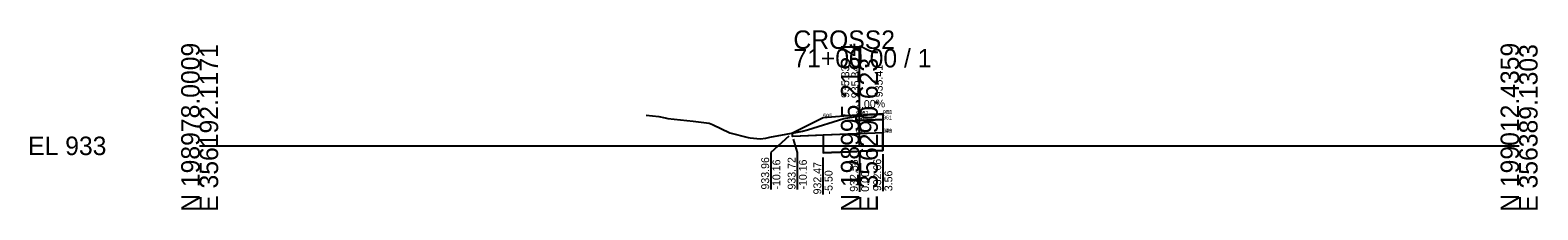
# Model space of a CAD drawing. Extents: x -26 to 203, y -10 to 14021.
# Drawn here: x -25.7 to 202.8, y 11990.3 to 12017.5 of the extents above; entities that cross this region are included whole.
import ezdxf

# ---------------------------------------------------------------- set-up
doc = ezdxf.new("R2010")
doc.units = 0
for name, color, linetype in [('Default', 7, 'Continuous'), ('P_E_XS_Ground', 7, 'Continuous'), ('P_XS', 7, 'Continuous'), ('P_XS_Bold', 7, 'Continuous'), ('P_XS_EAR_CommonGrnd', 7, 'Continuous'), ('P_XS_Lane', 7, 'Continuous'), ('P_XS_Rock', 7, 'Continuous')]:
    doc.layers.add(name, color=color, linetype=linetype)

msp = doc.modelspace()

# ---------------------------------------------------------------- linework, layer by layer
at = {"layer": 'Default'}
for p, q in [((100, 12000), (100, 12014.68)), ((0, 12000), (100, 12000)), ((100, 12000), (200, 12000))]:
    msp.add_line(p, q, dxfattribs=at)
at = {"layer": 'P_E_XS_Ground'}
for p, q in [((101.22, 12004.71), (103.54, 12004.89)), ((103.54, 12004.89), (103.65, 12004.89)), ((67.67, 12004.66), (69.59, 12004.44)), ((69.59, 12004.44), (70.55, 12004.23)), ((70.55, 12004.23), (70.99, 12004.15)), ((70.99, 12004.15), (74.78, 12003.73)), ((74.78, 12003.73), (77.25, 12003.45)), ((77.25, 12003.45), (77.74, 12003.21)), ((77.74, 12003.21), (80.35, 12001.99)), ((92.15, 12002.41), (97.63, 12004.14)), ((97.63, 12004.14), (97.95, 12004.19)), ((97.95, 12004.19), (100, 12004.54)), ((100, 12004.54), (100.86, 12004.68)), ((100.86, 12004.68), (101.22, 12004.71)), ((80.35, 12001.99), (83.14, 12001.25)), ((83.14, 12001.25), (83.46, 12001.2)), ((83.46, 12001.2), (84.95, 12001.07)), ((84.95, 12001.07), (85.84, 12001.14)), ((85.84, 12001.14), (86.45, 12001.31)), ((86.45, 12001.31), (91.39, 12002.2)), ((91.39, 12002.2), (92.15, 12002.41))]:
    msp.add_line(p, q, dxfattribs=at)
at = {"layer": 'P_XS'}
for p, q in [((99.5, 12004.65), (99.5, 12003.82)), ((99.5, 12003.82), (100, 12003.84)), ((103.56, 12003.98), (100, 12003.84)), ((103.56, 12004.81), (103.56, 12003.98)), ((103.56, 12003.98), (103.56, 12001.98)), ((89.84, 12001.43), (89.84, 12001.92)), ((99.5, 12001.82), (89.84, 12001.43)), ((94.5, 12001.62), (94.5, 11998.95)), ((99.5, 12001.82), (100, 12001.84)), ((103.56, 12001.98), (100, 12001.84)), ((103.56, 12001.98), (103.56, 11999.31)), ((99.61, 11999.15), (94.5, 11998.95)), ((99.61, 11999.15), (100.11, 11999.17)), ((103.56, 11999.31), (100.1, 11999.17))]:
    msp.add_line(p, q, dxfattribs=at)
at = {"layer": 'P_XS_EAR_CommonGrnd'}
for points in [[(101.54, 12004.73), (103.54, 12004.89), (103.56, 12004.89), (103.56, 12004.81)], [(94.5, 12004.25), (89.84, 12001.92), (91.39, 12002.2), (92.15, 12002.41), (97.63, 12004.14), (97.95, 12004.19), (99.5, 12004.45), (99.5, 12004.65)], [(103.56, 12003.98), (103.56, 12001.98), (100, 12001.84), (99.5, 12001.82), (94.5, 12001.62), (89.84, 12001.43), (89.84, 12001.92), (91.39, 12002.2), (92.15, 12002.41), (97.63, 12004.14), (97.95, 12004.19), (99.5, 12004.45), (99.5, 12003.82), (100, 12003.84)], [(100.86, 12004.68), (101.22, 12004.71), (101.54, 12004.73), (103.56, 12004.81), (103.56, 12003.98), (100, 12003.84), (99.5, 12003.82), (99.5, 12004.45), (100, 12004.54)], [(100, 12004.67), (101.54, 12004.73), (101.22, 12004.71), (100.86, 12004.68), (100, 12004.54), (99.5, 12004.45), (99.5, 12004.65)], [(99.61, 11999.15), (100.1, 11999.17), (103.56, 11999.31), (103.56, 12001.98), (100, 12001.84), (99.5, 12001.82), (94.5, 12001.62), (94.5, 11998.95)]]:
    msp.add_lwpolyline(points, close=True, dxfattribs=at)
at = {"layer": 'P_XS_Lane'}
for p, q in [((103.56, 12004.81), (103.56, 12004.89)), ((94.5, 12004.25), (89.84, 12001.92)), ((99.5, 12004.65), (94.5, 12004.25)), ((99.5, 12004.65), (100, 12004.67)), ((100, 12004.67), (103.56, 12004.81))]:
    msp.add_line(p, q, dxfattribs=at)
at = {"layer": 'P_XS_Rock'}
for p, q in [((89.31, 12001.45), (86.57, 11998.99)), ((89.96, 12001.03), (90.58, 11998.97)), ((86.57, 11998.99), (86.57, 11993.38)), ((90.58, 11998.97), (90.58, 11993.38)), ((94.48, 11998.23), (94.48, 11992.64)), ((100.01, 11998.64), (100.01, 11993.04)), ((103.55, 11998.72), (103.55, 11993.12))]:
    msp.add_line(p, q, dxfattribs=at)

# ---------------------------------------------------------------- texts
at = {"layer": 'Default'}
for s, p in [('CROSS2', (90, 12014.68)), ('71+00.00 / 1', (90, 12011.88)), ('EL 933', (-26, 11998.6))]:
    msp.add_text(s, height=2.8, dxfattribs=at).set_placement(p)
for s, p in [('N 198978.0009', (0, 11990)), ('E 356192.1171', (2.8, 11990)), ('N 198995.2184', (100, 11990)), ('E 356290.6237', (102.8, 11990)), ('N 199012.4359', (200, 11990)), ('E 356389.1303', (202.8, 11990))]:
    msp.add_text(s, height=2.8, rotation=90, dxfattribs=at).set_placement(p)
at = {"layer": 'P_XS_Bold'}
for s, p in [('505', (94.5, 12004.25)), ('951', (99.5, 12004.65)), ('9', (99.5, 12004.65)), ('900', (99.5, 12004.65)), ('952', (100, 12004.67)), ('952', (100, 12004.67)), ('951', (103.56, 12004.81)), ('9', (103.56, 12004.81)), ('900', (103.56, 12004.81)), ('910', (103.56, 12004.81)), ('961', (99.5, 12003.82)), ('962', (100, 12003.84)), ('962', (100, 12003.84)), ('961', (103.56, 12003.98)), ('971', (103.56, 12001.98)), ('998', (103.56, 12001.98)), ('540', (103.56, 12001.98)), ('971', (99.5, 12001.82)), ('998', (99.5, 12001.82)), ('972', (100, 12001.84)), ('972', (100, 12001.84))]:
    msp.add_text(s, height=0.6, dxfattribs=at).set_placement(p)
at = {"layer": 'P_XS_Rock'}
for s, rotation, p in [('935.33', 90, (98.46, 12007.25)), ('935.34', 90, (99.98, 12007.22)), ('935.34', 90, (99.98, 12007.22)), ('935.34', 90, (99.98, 12007.22)), ('935.34', 90, (99.98, 12007.22)), ('935.41', 90, (103.53, 12007.36)), ('2.00%', 2.2906, (99.37, 12005.65)), ('933.96', 90, (86.32, 11993.38)), ('933.72', 90, (90.33, 11993.38)), ('932.66', 90, (103.3, 11993.13)), ('-10.16', 90, (88.02, 11993.38)), ('-10.16', 90, (92.03, 11993.38)), ('932.47', 90, (94.23, 11992.64)), ('-5.50', 90, (95.93, 11992.64)), ('932.58', 90, (99.76, 11993.04)), ('0.00', 90, (101.46, 11993.04)), ('3.56', 90, (105, 11993.13))]:
    msp.add_text(s, height=1.2, rotation=rotation, dxfattribs=at).set_placement(p)

doc.saveas('drawing.dxf')
